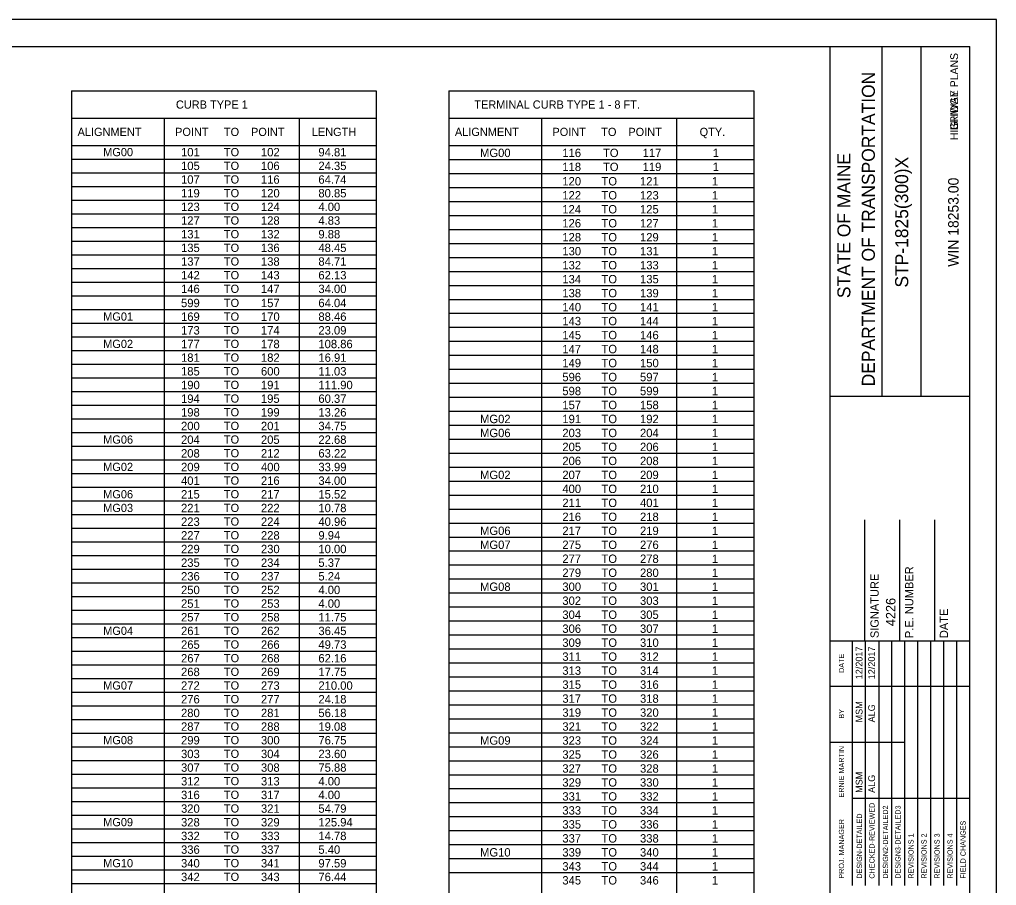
# Model space of a CAD drawing. Extents: x -415 to 632, y -278 to 272.
# Drawn here: x 85.1 to 434.5, y -37.5 to 272.2 of the extents above; entities that cross this region are included whole.
import ezdxf

# ---------------------------------------------------------------- set-up
doc = ezdxf.new("R2010")
doc.units = 0
for name, color, linetype in [('ANNOTATION', 7, 'Continuous'), ('BORDER', 7, 'Continuous'), ('BRIDGE_TITLE', 7, 'Continuous'), ('H_V CONTROLS', 7, 'Continuous'), ('HIGHWAY_TITLE', 7, 'Continuous'), ('PLOT BOUNDARY', 7, 'Continuous')]:
    doc.layers.add(name, color=color, linetype=linetype)

msp = doc.modelspace()

# ---------------------------------------------------------------- linework, layer by layer
at = {"layer": 'BORDER'}
for p, q in [((425, 262.5), (-375, 262.5)), ((375, -262.5), (375, 262.5)), ((393.64, 137.49), (393.64, 262.49)), ((407.62, 137.49), (407.62, 262.49)), ((425, -262.49), (425, 262.51)), ((375, 137.47), (425, 137.47)), ((387.5, 50.01), (387.5, 93.25)), ((400, 50.01), (400, 93.25)), ((412.5, 50.01), (412.5, 93.25)), ((375, 50.01), (425, 50.01))]:
    msp.add_line(p, q, dxfattribs=at)
for points in [[(383.07, 33.76), (383.07, 50.01)], [(387.74, -37.47), (387.74, 50.01)], [(392.4, 50.01), (392.4, -37.47)], [(397.05, -37.47), (397.05, 50.01)], [(401.71, -37.47), (401.71, 50.01)], [(406.37, -37.47), (406.37, 50.01)], [(411.03, -37.47), (411.03, 50.01)], [(415.69, -37.47), (415.69, 50.01)], [(420.35, -37.47), (420.35, 50.01)], [(383.08, -37.47), (383.08, 46.48)], [(375, 33.76), (425, 33.76)], [(375, 13.76), (383.08, 13.76)], [(383.07, 13.76), (401.71, 13.76)], [(383.07, -6.24), (425, -6.24)]]:
    msp.add_lwpolyline(points, dxfattribs=at)
at = {"layer": 'H_V CONTROLS'}
for p, q in [((103.65, 246.69), (103.65, -110.1)), ((103.65, 246.69), (212.69, 246.69)), ((212.69, 246.69), (212.69, -110.1)), ((238.63, 246.69), (347.68, 246.69)), ((238.63, 246.69), (238.63, -132.86)), ((347.68, 246.69), (347.68, -132.86)), ((103.65, 236.92), (212.69, 236.92)), ((136.79, 236.92), (136.79, -110.1)), ((185.09, 236.92), (185.09, -110.1)), ((238.63, 236.92), (347.68, 236.92)), ((271.78, 236.92), (271.78, -132.86)), ((320.08, 236.92), (320.08, -132.86)), ((103.65, 227.14), (212.69, 227.14)), ((238.63, 227.14), (347.68, 227.14)), ((238.63, 227.14), (347.68, 227.14)), ((103.65, 222.25), (212.69, 222.25)), ((238.63, 222.14), (347.68, 222.14)), ((103.65, 217.37), (212.69, 217.37)), ((238.63, 217.14), (347.68, 217.14)), ((103.65, 212.48), (212.69, 212.48)), ((238.63, 212.14), (347.68, 212.14)), ((103.65, 207.59), (212.69, 207.59)), ((238.63, 207.14), (347.68, 207.14)), ((103.65, 202.7), (212.69, 202.7)), ((238.63, 202.14), (347.68, 202.14)), ((103.65, 197.82), (212.69, 197.82)), ((238.63, 197.14), (347.68, 197.14)), ((103.65, 192.93), (212.69, 192.93)), ((238.63, 192.14), (347.68, 192.14)), ((103.65, 188.04), (212.69, 188.04)), ((238.63, 187.14), (347.68, 187.14)), ((103.65, 183.15), (212.69, 183.15)), ((238.63, 182.14), (347.68, 182.14)), ((103.65, 178.27), (212.69, 178.27)), ((238.63, 177.14), (347.68, 177.14)), ((103.65, 173.38), (212.69, 173.38)), ((238.63, 172.14), (347.68, 172.14)), ((103.65, 168.49), (212.69, 168.49)), ((238.63, 167.14), (347.68, 167.14)), ((103.65, 163.6), (212.69, 163.6)), ((238.63, 162.14), (347.68, 162.14)), ((103.65, 158.72), (212.69, 158.72)), ((103.65, 153.83), (212.69, 153.83)), ((238.63, 157.14), (347.68, 157.14)), ((238.63, 152.14), (347.68, 152.14)), ((103.65, 148.94), (212.69, 148.94)), ((238.63, 147.14), (347.68, 147.14)), ((103.65, 144.05), (212.69, 144.05)), ((238.63, 142.14), (347.68, 142.14)), ((103.65, 139.17), (212.69, 139.17)), ((238.63, 137.14), (347.68, 137.14)), ((103.65, 134.28), (212.69, 134.28)), ((103.65, 129.39), (212.69, 129.39)), ((238.63, 132.14), (347.68, 132.14)), ((238.63, 127.14), (347.68, 127.14)), ((103.65, 124.5), (212.69, 124.5)), ((103.65, 119.62), (212.69, 119.62)), ((238.63, 122.14), (347.68, 122.14)), ((238.63, 117.14), (347.68, 117.14)), ((103.65, 114.73), (212.69, 114.73)), ((238.63, 112.14), (347.68, 112.14)), ((103.65, 109.84), (212.69, 109.84)), ((103.65, 104.95), (212.69, 104.95)), ((238.63, 107.14), (347.68, 107.14)), ((238.63, 102.14), (347.68, 102.14)), ((103.65, 100.07), (212.69, 100.07)), ((103.65, 95.18), (212.69, 95.18)), ((238.63, 97.14), (347.68, 97.14)), ((238.63, 92.14), (347.68, 92.14)), ((103.65, 90.29), (212.69, 90.29)), ((103.65, 85.4), (212.69, 85.4)), ((238.63, 87.14), (347.68, 87.14)), ((103.65, 80.52), (212.69, 80.52)), ((238.63, 82.14), (347.68, 82.14)), ((238.63, 82.14), (347.68, 82.14)), ((238.63, 77.14), (347.68, 77.14)), ((103.65, 75.63), (212.69, 75.63)), ((103.65, 70.74), (212.69, 70.74)), ((238.63, 72.14), (347.68, 72.14)), ((238.63, 67.14), (347.68, 67.14)), ((103.65, 65.85), (212.69, 65.85)), ((103.65, 60.97), (212.69, 60.97)), ((238.63, 62.14), (347.68, 62.14)), ((103.65, 56.08), (212.69, 56.08)), ((238.63, 57.14), (347.68, 57.14)), ((103.65, 51.19), (212.69, 51.19)), ((238.63, 52.14), (347.68, 52.14)), ((103.65, 46.3), (212.69, 46.3)), ((238.63, 47.14), (347.68, 47.14)), ((238.63, 42.14), (347.68, 42.14)), ((103.65, 41.42), (212.69, 41.42)), ((103.65, 36.53), (212.69, 36.53)), ((238.63, 37.14), (347.68, 37.14)), ((103.65, 31.64), (212.69, 31.64)), ((238.63, 32.14), (347.68, 32.14)), ((103.65, 26.75), (212.69, 26.75)), ((238.63, 27.14), (347.68, 27.14)), ((103.65, 21.87), (212.69, 21.87)), ((238.63, 22.14), (347.68, 22.14)), ((103.65, 16.98), (212.69, 16.98)), ((238.63, 17.14), (347.68, 17.14)), ((103.65, 12.09), (212.69, 12.09)), ((238.63, 12.14), (347.68, 12.14)), ((103.65, 7.2), (212.69, 7.2)), ((238.63, 7.14), (347.68, 7.14)), ((103.65, 2.32), (212.69, 2.32)), ((238.63, 2.14), (347.68, 2.14)), ((103.65, -2.57), (212.69, -2.57)), ((238.63, -2.86), (347.68, -2.86)), ((103.65, -7.46), (212.69, -7.46)), ((238.63, -7.86), (347.68, -7.86)), ((103.65, -12.35), (212.69, -12.35)), ((238.63, -12.86), (347.68, -12.86)), ((103.65, -17.23), (212.69, -17.23)), ((238.63, -17.86), (347.68, -17.86)), ((103.65, -22.12), (212.69, -22.12)), ((238.63, -22.86), (347.68, -22.86)), ((103.65, -27.01), (212.69, -27.01)), ((238.63, -27.86), (347.68, -27.86)), ((103.65, -31.9), (212.69, -31.9)), ((238.63, -32.86), (347.68, -32.86)), ((103.65, -36.78), (212.69, -36.78))]:
    msp.add_line(p, q, dxfattribs=at)
at = {"layer": 'PLOT BOUNDARY'}
msp.add_lwpolyline([(-415.47, -277.8), (434.53, -277.8), (434.53, 272.2), (-415.47, 272.2)], close=True, dxfattribs=at)

# ---------------------------------------------------------------- texts
at = {"layer": 'ANNOTATION'}
for s, height, rotation, p in [('MG00', 2.932, 360, (114.99, 223.33)), ('TO', 2.932, 360, (158.17, 223.33)), ('TO', 2.932, 360, (158.17, 218.44)), ('TO', 2.932, 360, (158.17, 213.55)), ('TO', 2.932, 360, (158.17, 208.67)), ('TO', 2.932, 360, (158.17, 203.78)), ('TO', 2.932, 360, (158.17, 198.89)), ('TO', 2.932, 360, (158.17, 194)), ('TO', 2.932, 360, (158.17, 189.12)), ('TO', 2.932, 360, (158.17, 184.23)), ('TO', 2.932, 360, (158.17, 179.34)), ('TO', 2.932, 360, (158.17, 174.45)), ('TO', 2.932, 360, (158.17, 169.41)), ('MG01', 2.932, 360, (114.99, 164.52)), ('TO', 2.932, 360, (158.17, 164.52)), ('TO', 2.932, 360, (158.17, 159.64)), ('MG02', 2.932, 360, (114.99, 154.74)), ('TO', 2.932, 360, (158.17, 154.75)), ('TO', 2.932, 360, (158.17, 149.85)), ('TO', 2.932, 360, (158.17, 144.97)), ('TO', 2.932, 360, (158.17, 140.09)), ('TO', 2.932, 360, (158.17, 135.2)), ('TO', 2.932, 360, (158.17, 130.31)), ('TO', 2.932, 360, (158.17, 125.42)), ('MG06', 2.932, 360, (114.99, 120.52)), ('TO', 2.932, 360, (158.17, 120.54)), ('TO', 2.932, 360, (158.17, 115.65)), ('MG02', 2.932, 360, (114.99, 110.75)), ('TO', 2.932, 360, (158.17, 110.76)), ('TO', 2.932, 360, (158.17, 105.86)), ('MG06', 2.932, 360, (114.99, 100.97)), ('TO', 2.932, 360, (158.17, 100.99)), ('MG03', 2.932, 360, (114.99, 96.08)), ('TO', 2.932, 360, (158.17, 96.1)), ('TO', 2.932, 360, (158.17, 91.21)), ('TO', 2.932, 360, (158.17, 86.32)), ('TO', 2.932, 360, (158.17, 81.44)), ('TO', 2.932, 360, (158.17, 76.55)), ('TO', 2.932, 360, (158.17, 71.68)), ('TO', 2.932, 360, (158.17, 66.81)), ('TO', 2.932, 360, (158.17, 61.92)), ('4226', 3.396, 90, (398.4, 55.26)), ('TO', 2.932, 360, (158.17, 57.04)), ('MG04', 2.932, 360, (114.99, 52.13)), ('TO', 2.932, 360, (158.17, 52.15)), ('TO', 2.932, 360, (158.17, 47.26)), ('TO', 2.932, 360, (158.17, 42.37)), ('TO', 2.932, 360, (158.17, 37.49)), ('MG07', 2.932, 360, (114.99, 32.58)), ('TO', 2.932, 360, (158.17, 32.6)), ('TO', 2.932, 360, (158.17, 27.71)), ('TO', 2.932, 360, (158.17, 22.82)), ('TO', 2.932, 360, (158.17, 17.94)), ('MG08', 2.932, 360, (114.99, 13.02)), ('TO', 2.932, 360, (158.17, 13.05)), ('TO', 2.932, 360, (158.17, 8.16)), ('TO', 2.932, 360, (158.17, 3.27)), ('TO', 2.932, 360, (158.17, -1.61)), ('TO', 2.932, 360, (158.17, -6.5)), ('TO', 2.932, 360, (158.17, -11.39)), ('MG09', 2.932, 360, (114.99, -16.3)), ('TO', 2.932, 360, (158.17, -16.28)), ('TO', 2.932, 360, (158.17, -21.16)), ('TO', 2.932, 360, (158.17, -26.05)), ('MG10', 2.932, 360, (114.99, -30.97)), ('TO', 2.932, 360, (158.17, -30.94)), ('TO', 2.932, 360, (158.17, -35.83))]:
    msp.add_text(s, height=height, rotation=rotation, dxfattribs=at).set_placement(p)
for s, p in [('101', (142.83, 223.26)), ('102', (171.42, 223.26)), ('94.81', (191.97, 223.26)), ('MG00', (249.79, 223.02)), ('116', (279.24, 223.02)), ('TO', (293.77, 223.02)), ('117', (307.97, 223.02)), ('1', (333.03, 223.02)), ('105', (142.83, 218.37)), ('106', (171.42, 218.37)), ('24.35', (191.97, 218.37)), ('118', (279.24, 218.02)), ('TO', (293.77, 218.02)), ('119', (307.97, 218.02)), ('1', (333.03, 218.02)), ('107', (142.83, 213.49)), ('116', (171.42, 213.49)), ('64.74', (191.97, 213.49)), ('120', (279.24, 212.86)), ('TO', (293.24, 212.86)), ('121', (307.02, 212.86)), ('1', (332.76, 212.86)), ('119', (142.83, 208.6)), ('120', (171.42, 208.6)), ('80.85', (191.97, 208.6)), ('122', (279.24, 207.86)), ('TO', (293.24, 207.86)), ('123', (307.02, 207.86)), ('1', (332.76, 207.86)), ('123', (142.83, 203.71)), ('124', (171.42, 203.71)), ('4.00', (191.97, 203.71)), ('124', (279.24, 202.86)), ('TO ', (293.24, 202.86)), ('125', (307.02, 202.86)), ('1 ', (332.76, 202.86)), ('127', (142.83, 198.82)), ('128', (171.42, 198.82)), ('4.83', (191.97, 198.82)), ('126', (279.24, 197.86)), ('TO', (293.24, 197.86)), ('127', (307.02, 197.86)), ('1', (332.76, 197.86)), ('131', (142.83, 193.93)), ('132', (171.42, 193.93)), ('9.88', (191.97, 193.93)), ('128', (279.24, 192.86)), ('TO ', (293.24, 192.86)), ('129', (307.02, 192.86)), ('1 ', (332.76, 192.86)), ('135', (142.83, 189.05)), ('136', (171.42, 189.05)), ('48.45', (191.97, 189.05)), ('130', (279.24, 187.86)), ('TO', (293.24, 187.86)), ('131', (307.02, 187.86)), ('1', (332.76, 187.86)), ('137', (142.83, 184.16)), ('138', (171.42, 184.16)), ('84.71', (191.97, 184.16)), ('132', (279.24, 182.86)), ('TO', (293.24, 182.86)), ('133', (307.02, 182.86)), ('1', (332.76, 182.86)), ('142', (142.83, 179.27)), ('143', (171.42, 179.27)), ('62.13', (191.97, 179.27)), ('134', (279.24, 177.86)), ('TO', (293.24, 177.86)), ('135', (307.02, 177.86)), ('1', (332.76, 177.86)), ('146', (142.83, 174.38)), ('147', (171.42, 174.38)), ('34.00', (191.97, 174.38)), ('138', (279.24, 172.86)), ('TO', (293.24, 172.86)), ('139', (307.02, 172.86)), ('1', (332.76, 172.86)), ('599', (142.83, 169.34)), ('157', (171.42, 169.34)), ('64.04', (191.97, 169.34)), ('140', (279.24, 167.86)), ('TO', (293.24, 167.86)), ('141', (307.02, 167.86)), ('1', (332.76, 167.86)), ('169', (142.83, 164.45)), ('170', (171.42, 164.45)), ('88.46', (191.97, 164.45)), ('143', (279.24, 162.86)), ('TO', (293.24, 162.86)), ('144', (307.02, 162.86)), ('1', (332.76, 162.86)), ('173', (142.83, 159.56)), ('174', (171.42, 159.56)), ('23.09', (191.97, 159.56)), ('145', (279.24, 157.86)), ('TO', (293.24, 157.86)), ('146', (307.02, 157.86)), ('1', (332.76, 157.86)), ('177', (142.83, 154.67)), ('178', (171.42, 154.67)), ('108.86', (191.97, 154.67)), ('147', (279.24, 152.86)), ('TO', (293.24, 152.86)), ('148', (307.02, 152.86)), ('1', (332.76, 152.86)), ('181', (142.83, 149.79)), ('182', (171.42, 149.79)), ('16.91', (191.97, 149.79)), ('149', (279.24, 147.86)), ('TO', (293.24, 147.86)), ('150', (307.02, 147.86)), ('1', (332.76, 147.86)), ('185', (142.83, 144.91)), ('600', (171.42, 144.9)), ('11.03', (191.97, 144.9)), ('596', (279.24, 142.86)), ('TO', (293.24, 142.86)), ('597', (307.02, 142.86)), ('1', (332.76, 142.86)), ('190', (142.83, 140.01)), ('191', (171.42, 140.01)), ('111.90', (191.97, 140.01)), ('598', (279.24, 137.86)), ('TO', (293.24, 137.86)), ('599', (307.02, 137.86)), ('1', (332.76, 137.86)), ('194', (142.83, 135.12)), ('195', (171.42, 135.12)), ('60.37', (191.97, 135.12)), ('198', (142.83, 130.23)), ('199', (171.42, 130.23)), ('13.26', (191.97, 130.23)), ('157', (279.24, 132.86)), ('TO', (293.24, 132.86)), ('158', (307.02, 132.86)), ('1', (332.76, 132.86)), ('MG02', (249.79, 127.86)), ('191', (279.24, 127.86)), ('TO', (293.24, 127.86)), ('192', (307.02, 127.86)), ('1', (332.76, 127.86)), ('200', (142.83, 125.35)), ('201', (171.42, 125.35)), ('34.75', (191.97, 125.35)), ('MG06', (249.79, 122.86)), ('203', (279.24, 122.86)), ('TO', (293.24, 122.86)), ('204', (307.02, 122.86)), ('1', (332.76, 122.86)), ('204', (142.83, 120.46)), ('205', (171.42, 120.46)), ('22.68', (191.97, 120.46)), ('205', (279.24, 117.86)), ('TO', (293.24, 117.86)), ('206', (307.02, 117.86)), ('1', (332.76, 117.86)), ('208', (142.83, 115.57)), ('212', (171.42, 115.57)), ('63.22', (191.97, 115.57)), ('206', (279.24, 112.86)), ('TO', (293.24, 112.86)), ('208', (307.02, 112.86)), ('1', (332.76, 112.86)), ('209', (142.83, 110.68)), ('400', (171.42, 110.68)), ('33.99', (191.97, 110.68)), ('401', (142.83, 105.79)), ('216', (171.42, 105.79)), ('34.00', (191.97, 105.79)), ('MG02', (249.79, 107.86)), ('207', (279.24, 107.86)), ('TO', (293.24, 107.86)), ('209', (307.02, 107.86)), ('1', (332.76, 107.86)), ('400', (279.24, 102.86)), ('TO', (293.24, 102.86)), ('210', (307.02, 102.86)), ('1', (332.76, 102.86)), ('215', (142.83, 100.91)), ('217', (171.42, 100.91)), ('15.52', (191.97, 100.91)), ('221', (142.83, 96.02)), ('222', (171.42, 96.02)), ('10.78', (191.97, 96.02)), ('211', (279.24, 97.86)), ('TO', (293.24, 97.86)), ('401', (307.02, 97.86)), ('1', (332.76, 97.86)), ('216', (279.24, 92.86)), ('TO', (293.24, 92.86)), ('218', (307.02, 92.86)), ('1', (332.76, 92.86)), ('223', (142.83, 91.13)), ('224', (171.42, 91.13)), ('40.96', (191.97, 91.13)), ('MG06', (249.79, 87.86)), ('217', (279.24, 87.86)), ('TO', (293.24, 87.86)), ('219', (307.02, 87.86)), ('227', (142.83, 86.24)), ('228', (171.42, 86.24)), ('9.94', (191.97, 86.24)), ('1', (332.76, 87.86)), ('229', (142.83, 81.35)), ('230', (171.42, 81.35)), ('10.00', (191.97, 81.35)), ('MG07', (249.79, 82.86)), ('275', (279.24, 82.86)), ('TO', (293.24, 82.86)), ('276', (307.02, 82.86)), ('1', (332.76, 82.86)), ('277', (279.24, 77.86)), ('TO', (293.24, 77.86)), ('278', (307.02, 77.86)), ('1', (332.76, 77.86)), ('235', (142.83, 76.47)), ('234', (171.42, 76.47)), ('5.37', (191.97, 76.47)), ('236', (142.83, 71.59)), ('237', (171.42, 71.59)), ('5.24', (191.97, 71.59)), ('279', (279.24, 72.86)), ('TO', (293.24, 72.86)), ('280', (307.02, 72.86)), ('1', (332.76, 72.86)), ('MG08', (249.79, 67.86)), ('300', (279.24, 67.86)), ('TO', (293.24, 67.86)), ('301', (307.02, 67.86)), ('1', (332.76, 67.86)), ('250', (142.83, 66.72)), ('252', (171.42, 66.72)), ('4.00', (191.97, 66.72)), ('251', (142.83, 61.84)), ('253', (171.42, 61.84)), ('4.00', (191.97, 61.84)), ('302', (279.24, 62.86)), ('TO', (293.24, 62.86)), ('303', (307.02, 62.86)), ('1', (332.76, 62.86)), ('257', (142.83, 56.95)), ('258', (171.42, 56.95)), ('11.75', (191.97, 56.95)), ('304', (279.24, 57.86)), ('TO', (293.24, 57.86)), ('305', (307.02, 57.86)), ('1', (332.76, 57.86)), ('261', (142.83, 52.06)), ('262', (171.42, 52.06)), ('36.45', (191.97, 52.06)), ('306', (279.24, 52.86)), ('TO', (293.24, 52.86)), ('307', (307.02, 52.86)), ('1', (332.76, 52.86)), ('265', (142.83, 47.17)), ('266', (171.42, 47.17)), ('49.73', (191.97, 47.17)), ('309', (279.24, 47.86)), ('TO', (293.24, 47.86)), ('310', (307.02, 47.86)), ('1', (332.76, 47.86)), ('311', (279.24, 42.86)), ('TO', (293.24, 42.86)), ('312', (307.02, 42.86)), ('1', (332.76, 42.86)), ('267', (142.83, 42.28)), ('268', (171.42, 42.28)), ('62.16', (191.97, 42.28)), ('268', (142.83, 37.4)), ('269', (171.42, 37.4)), ('17.75', (191.97, 37.4)), ('313', (279.24, 37.86)), ('TO', (293.24, 37.86)), ('314', (307.02, 37.86)), ('1', (332.76, 37.86)), ('272', (142.83, 32.51)), ('273', (171.42, 32.51)), ('210.00', (191.97, 32.51)), ('315', (279.24, 32.86)), ('TO', (293.24, 32.86)), ('316', (307.02, 32.86)), ('1', (332.76, 32.86)), ('276', (142.83, 27.62)), ('277', (171.42, 27.62)), ('24.18', (191.97, 27.62)), ('317', (279.24, 27.86)), ('TO', (293.24, 27.86)), ('318', (307.02, 27.86)), ('1', (332.76, 27.86)), ('280', (142.83, 22.73)), ('281', (171.42, 22.73)), ('56.18', (191.97, 22.73)), ('319', (279.24, 22.86)), ('TO', (293.24, 22.86)), ('320', (307.02, 22.86)), ('1', (332.76, 22.86)), ('287', (142.83, 17.84)), ('288', (171.42, 17.84)), ('19.08', (191.97, 17.84)), ('321', (279.24, 17.86)), ('TO', (293.24, 17.86)), ('322', (307.02, 17.86)), ('1', (332.76, 17.86)), ('299', (142.83, 12.96)), ('300', (171.42, 12.96)), ('76.75', (191.97, 12.96)), ('MG09', (249.79, 12.86)), ('323', (279.24, 12.86)), ('TO', (293.24, 12.86)), ('324', (307.02, 12.86)), ('1', (332.76, 12.86)), ('303', (142.83, 8.07)), ('304', (171.42, 8.07)), ('23.60', (191.97, 8.07)), ('325', (279.24, 7.86)), ('TO', (293.24, 7.86)), ('326', (307.02, 7.86)), ('1', (332.76, 7.86)), ('307', (142.83, 3.18)), ('308', (171.42, 3.18)), ('75.88', (191.97, 3.18)), ('327', (279.24, 2.86)), ('TO', (293.24, 2.86)), ('328', (307.02, 2.86)), ('1', (332.76, 2.86)), ('312', (142.83, -1.71)), ('313', (171.42, -1.71)), ('4.00', (191.97, -1.71)), ('329', (279.24, -2.14)), ('TO', (293.24, -2.14)), ('330', (307.02, -2.14)), ('1', (332.76, -2.14)), ('316', (142.83, -6.6)), ('317', (171.42, -6.6)), ('4.00', (191.97, -6.6)), ('331', (279.24, -7.14)), ('TO', (293.24, -7.14)), ('332', (307.02, -7.14)), ('1', (332.76, -7.14)), ('320', (142.83, -11.48)), ('321', (171.42, -11.48)), ('54.79', (191.97, -11.48)), ('333', (279.24, -12.14)), ('TO', (293.24, -12.14)), ('334', (307.02, -12.14)), ('1', (332.76, -12.14)), ('328', (142.83, -16.37)), ('329', (171.42, -16.37)), ('125.94', (191.97, -16.37)), ('335', (279.24, -17.14)), ('TO', (293.24, -17.14)), ('336', (307.02, -17.14)), ('1', (332.76, -17.14)), ('332', (142.83, -21.26)), ('333', (171.42, -21.26)), ('14.78', (191.97, -21.26)), ('337', (279.24, -22.14)), ('TO', (293.24, -22.14)), ('338', (307.02, -22.14)), ('1', (332.76, -22.14)), ('336', (142.83, -26.15)), ('337', (171.42, -26.15)), ('5.40', (191.97, -26.15)), ('MG10', (249.79, -27.14)), ('339', (279.24, -27.14)), ('TO', (293.24, -27.14)), ('340', (307.02, -27.14)), ('1', (332.76, -27.14)), ('340', (142.83, -31.04)), ('341', (171.42, -31.04)), ('97.59', (191.97, -31.04)), ('343', (279.24, -32.14)), ('TO', (293.24, -32.14)), ('344', (307.02, -32.14)), ('1', (332.76, -32.14)), ('342', (142.83, -35.92)), ('343', (171.42, -35.92)), ('76.44', (191.97, -35.92)), ('345', (279.24, -37.14)), ('TO', (293.24, -37.14)), ('346', (307.02, -37.14)), ('1', (332.76, -37.14))]:
    msp.add_text(s, height=3, dxfattribs=at).set_placement(p)
at = {"layer": 'BORDER'}
for s, height, p in [('DEPARTMENT OF TRANSPORTATION', 4.6588, (391.03, 141.03)), ('STATE OF MAINE', 4.6588, (382.28, 172.56)), ('STP-1825(300)X', 4.6588, (402.96, 176.36)), ('WIN 18253.00', 3.7264, (420.98, 183.8)), ('SIGNATURE', 2.953, (392.4, 50.98)), ('P.E. NUMBER', 2.9528, (404.8, 50.98)), ('DATE', 2.953, (417.21, 50.98)), ('12/2017', 2.423, (386.61, 36.26)), ('12/2017', 2.423, (391.09, 36.26)), ('DATE', 1.857, (380.02, 38.54)), ('MSM', 2.423, (386.61, 20.84)), ('BY', 1.857, (380.02, 22.19)), ('ALG', 2.423, (391.09, 20.84)), ('ERNIE MARTIN', 1.8637, (380.02, -6.03)), ('MSM', 2.423, (386.61, -4.37)), ('ALG', 2.423, (391.09, -4.37)), ('CHECKED-REVIEWED', 1.8637, (390.91, -35.04)), ('DESIGN2-DETAILED2', 1.8637, (395.75, -35.04)), ('DESIGN3-DETAILED3', 1.8637, (400.22, -35.04)), ('DESIGN-DETAILED', 1.8637, (386.43, -35.04)), ('PROJ. MANAGER', 1.8637, (380.02, -35.04)), ('FIELD CHANGES', 1.8637, (423.51, -35.04)), ('REVISIONS 1', 1.8637, (404.88, -35.04)), ('REVISIONS 2', 1.8637, (409.54, -35.04)), ('REVISIONS 3', 1.8637, (414.2, -35.04)), ('REVISIONS 4', 1.8637, (418.86, -35.04))]:
    msp.add_text(s, height=height, rotation=90, dxfattribs=at).set_placement(p)
at = {"layer": 'BRIDGE_TITLE'}
msp.add_text('BRIDGE PLANS', height=2.795, rotation=90, dxfattribs=at).set_placement((420.79, 232.62))
at = {"layer": 'H_V CONTROLS'}
for s, height, p in [('CURB TYPE 1', 2.9325, (141, 240.34)), ('TERMINAL CURB TYPE 1 - 8 FT.', 2.9325, (247.74, 240.34)), ('ALIGNMENT', 2.932, (105.82, 230.56)), ('POINT', 2.932, (140.71, 230.56)), ('TO', 2.932, (158.17, 230.56)), ('POINT', 2.932, (167.86, 230.56)), ('LENGTH', 2.932, (189.61, 230.56)), ('ALIGNMENT', 2.932, (240.8, 230.56)), ('POINT', 2.932, (275.69, 230.56)), ('TO', 2.932, (293.15, 230.56)), ('POINT', 2.932, (302.84, 230.56)), ('QTY.', 2.932, (328.34, 230.56))]:
    msp.add_text(s, height=height, rotation=360, dxfattribs=at).set_placement(p)
at = {"layer": 'HIGHWAY_TITLE'}
msp.add_text('HIGHWAY PLANS', height=2.795, rotation=90, dxfattribs=at).set_placement((420.79, 229.08))

doc.saveas('drawing.dxf')
